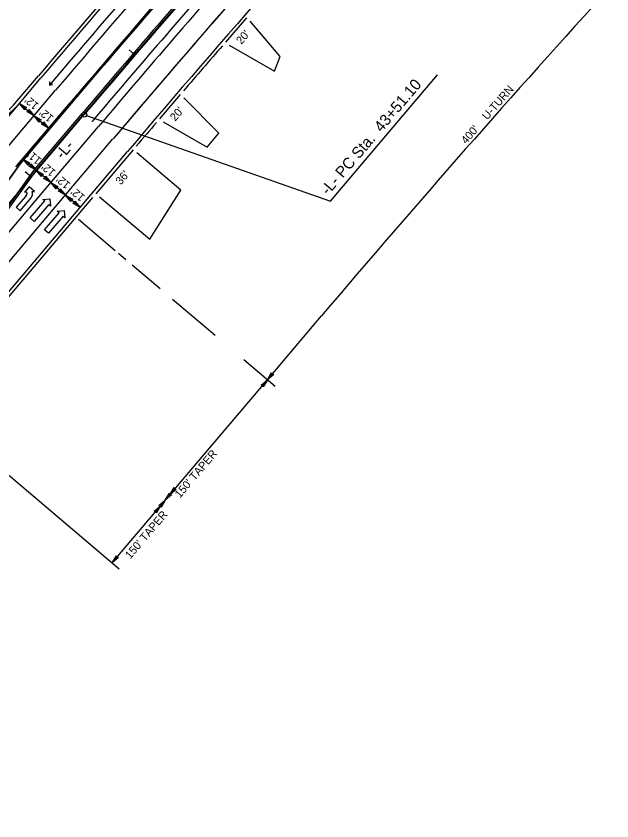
# Model space of a CAD drawing. Extents: x 1761082 to 1764358, y 421907 to 425434.
# Drawn here: x 1763418 to 1763790, y 424026 to 424529 of the extents above; entities that cross this region are included whole.
import ezdxf

# ---------------------------------------------------------------- set-up
doc = ezdxf.new("R2010")
doc.units = 0
for name, color, linetype in [('MARK HOOKS CENTER STRAIGHT LEFT TURN ARROW CELL', 7, 'Continuous'), ('MARK HOOKS STRAIGHT RIGHT TURN ARROW CELL', 7, 'Continuous'), ('MARK LEFT TURN ARROW CELL', 7, 'Continuous'), ('MARK ONLY WORD SYMBOL CELL', 7, 'Continuous'), ('MARK STRAIGHT RIGHT ARROW CELL', 7, 'Continuous'), ('MARK UTURN ARROW CELL', 7, 'Continuous'), ('Prop Conc Driveway', 7, 'Continuous'), ('Prop Mkg 3ft Min Skp 3ft Wide White', 7, 'Continuous'), ('Prop Mkg Skp Wht', 7, 'Continuous'), ('Prop Mkg Solid White Diagonals', 7, 'Continuous'), ('Prop Mkg Solid White Edge Line', 7, 'Continuous'), ('Prop Mkg Solid White Lane Line', 7, 'Continuous'), ('Prop Mkg Solid Yel Skip LT', 7, 'Continuous'), ('Prop Mkg Solid Yel Skip RT', 7, 'Continuous'), ('Prop Mkg Solid Yellow Diagonals', 7, 'Continuous'), ('Prop Mkg Solid Yellow Edge Line', 7, 'Continuous'), ('Prop Mkg Solid Yellow Lane Line', 7, 'Continuous'), ('Scratch_Level_0', 7, 'Continuous'), ('Scratch_Level_1', 7, 'Continuous')]:
    doc.layers.add(name, color=color, linetype=linetype)

msp = doc.modelspace()

# ---------------------------------------------------------------- linework, layer by layer
at = {"layer": 'MARK HOOKS CENTER STRAIGHT LEFT TURN ARROW CELL'}
for p, q in [((1763491.94, 424504.4), (1763488.15, 424507.65)), ((1763427.18, 424428.2), (1763423.37, 424431.43))]:
    msp.add_line(p, q, dxfattribs=at)
at = {"layer": 'MARK LEFT TURN ARROW CELL'}
for p, q in [((1763418.12, 424475.51), (1763431.6, 424491.43)), ((1763290.14, 424208.41), (1763465.55, 424415.48))]:
    msp.add_line(p, q, dxfattribs=at)
for centre, radius, start, end in [((1769289.17, 419529.14), 7676.94, 138.803366, 139.730103), ((1769289.17, 419529.14), 7601.94, 139.061862, 139.343024), ((1763381.5, 424506.54), 48, 261.3879, 319.7301), ((1769289.17, 419529.14), 7601.94, 139.538986, 139.684921)]:
    msp.add_arc(centre, radius, start, end, dxfattribs=at)
at = {"layer": 'MARK ONLY WORD SYMBOL CELL'}
for p, q in [((1763561.63, 424527.61), (1763548.5, 424512.52)), ((1763520.2, 424479.74), (1763507.2, 424464.55)), ((1763490.76, 424445.23), (1763467.49, 424417.76))]:
    msp.add_line(p, q, dxfattribs=at)
at = {"layer": 'MARK STRAIGHT RIGHT ARROW CELL'}
msp.add_line((1763060.78, 423995.7), (1763460.21, 424467.19), dxfattribs=at)
msp.add_arc((1769289.17, 419529.14), 7639.44, 137.617012, 139.730103, dxfattribs=at)
at = {"layer": 'MARK UTURN ARROW CELL'}
msp.add_lwpolyline([(1763461.63, 424466.69), (1763614.03, 424413.18), (1763680.83, 424492.03)], dxfattribs=at)
msp.add_circle((1763460.21, 424467.19), 1.5, dxfattribs=at)
at = {"layer": 'Prop Conc Driveway'}
for p, q in [((1763582.55, 424503.58), (1763563.89, 424525.64)), ((1763550.76, 424510.56), (1763579.06, 424494.39)), ((1763579.06, 424494.39), (1763582.55, 424503.58)), ((1763544.32, 424455.69), (1763522.48, 424477.79)), ((1763509.48, 424462.6), (1763537.04, 424446.86)), ((1763537.04, 424446.86), (1763544.32, 424455.69)), ((1763520.43, 424420.08), (1763493.05, 424443.29)), ((1763501.08, 424389.31), (1763520.43, 424420.08)), ((1763469.78, 424415.83), (1763501.08, 424389.31))]:
    msp.add_line(p, q, dxfattribs=at)
at = {"layer": 'Prop Mkg 3ft Min Skp 3ft Wide White'}
msp.add_line((1763060.78, 423995.7), (1763460.21, 424467.19), dxfattribs=at)
msp.add_arc((1769289.17, 419529.14), 7639.44, 137.617012, 139.730103, dxfattribs=at)
at = {"layer": 'Prop Mkg Skp Wht'}
for p, q in [((1763419.65, 424474.22), (1763433.13, 424490.13)), ((1763191.95, 424095.61), (1763487.3, 424444.24))]:
    msp.add_line(p, q, dxfattribs=at)
for centre, radius, start, end in [((1769289.17, 419529.14), 7603.94, 137.617012, 139.730103), ((1769289.17, 419529.14), 7674.94, 138.158837, 139.730103), ((1763381.5, 424506.54), 50, 261.3879, 319.7301)]:
    msp.add_arc(centre, radius, start, end, dxfattribs=at)
at = {"layer": 'Prop Mkg Solid White Diagonals'}
for p, q in [((1763452.01, 424474.14), (1763420.16, 424436.54)), ((1763429.37, 424433.1), (1763459.07, 424468.16)), ((1763420.16, 424436.54), (1763330.53, 424311.79)), ((1763335.43, 424303.26), (1763429.37, 424433.1))]:
    msp.add_line(p, q, dxfattribs=at)
for radius, start in [(7650.19, 137.617012), (7640.94, 138.645864)]:
    msp.add_arc((1769289.17, 419529.14), radius, start, 139.730103, dxfattribs=at)
at = {"layer": 'Prop Mkg Solid White Edge Line'}
msp.add_arc((1769289.17, 419529.14), 7615.94, 137.617012, 139.730103, dxfattribs=at)
at = {"layer": 'Prop Mkg Solid White Lane Line'}
for p, q in [((1763420.16, 424436.54), (1763452.01, 424474.14)), ((1763429.37, 424433.1), (1763459.07, 424468.16)), ((1763330.53, 424311.79), (1763420.16, 424436.54)), ((1763429.37, 424433.1), (1763335.43, 424303.26))]:
    msp.add_line(p, q, dxfattribs=at)
for radius in [7650.19, 7640.94]:
    msp.add_arc((1769289.17, 419529.14), radius, 138.645864, 139.730103, dxfattribs=at)
at = {"layer": 'Prop Mkg Solid Yel Skip RT'}
for p, q in [((1763419.65, 424474.22), (1763437.96, 424458.71)), ((1763457.62, 424409.21), (1763421.76, 424439.59)), ((1763479.44, 424382.18), (1763456.52, 424401.6)), ((1763486.21, 424376.45), (1763481.57, 424380.38)), ((1763507.52, 424358.39), (1763490.13, 424373.12)), ((1763542.04, 424329.15), (1763515.3, 424351.8)), ((1763574.58, 424301.58), (1763608.47, 424341.59)), ((1763579.49, 424297.42), (1763559.97, 424313.95)), ((1763477.62, 424187.13), (1763574.58, 424301.58)), ((1763482.07, 424183.36), (1763404.94, 424248.7))]:
    msp.add_line(p, q, dxfattribs=at)
msp.add_arc((1769289.17, 419529.14), 7445.13, 137.617012, 139.730103, dxfattribs=at)
at = {"layer": 'Prop Mkg Solid Yellow Diagonals'}
for p, q in [((1763425.88, 424422.16), (1763422.91, 424418.77)), ((1763429.19, 424419.26), (1763425.88, 424422.16)), ((1763422.91, 424418.77), (1763424.39, 424418.89)), ((1763427.71, 424419.14), (1763429.19, 424419.26)), ((1763423.64, 424416.24), (1763417.69, 424409.29)), ((1763420.19, 424407.14), (1763427.06, 424415.16)), ((1763426.4, 424402.63), (1763435.52, 424413.25)), ((1763434.39, 424414.23), (1763438.79, 424414.6)), ((1763435.52, 424413.25), (1763434.39, 424414.23)), ((1763438.79, 424414.6), (1763439.16, 424410.12)), ((1763417.69, 424409.29), (1763420.19, 424407.14)), ((1763438.03, 424411.1), (1763428.9, 424400.48)), ((1763439.16, 424410.12), (1763438.03, 424411.1)), ((1763443.31, 424406.85), (1763447.72, 424407.22)), ((1763447.72, 424407.22), (1763448.09, 424402.75)), ((1763428.9, 424400.48), (1763426.4, 424402.63)), ((1763435.33, 424395.25), (1763444.45, 424405.87)), ((1763446.95, 424403.72), (1763437.83, 424393.1)), ((1763444.45, 424405.87), (1763443.31, 424406.85)), ((1763448.09, 424402.75), (1763446.95, 424403.72)), ((1763437.83, 424393.1), (1763435.33, 424395.25))]:
    msp.add_line(p, q, dxfattribs=at)
for centre, radius, start, end in [((1763421.17, 424418.37), 3.27, 319.4106, 9.0688), ((1763422.61, 424417.92), 5.25, 328.0867, 13.3984)]:
    msp.add_arc(centre, radius, start, end, dxfattribs=at)
at = {"layer": 'Prop Mkg Solid Yellow Edge Line'}
for p, q in [((1763091.01, 424067.73), (1763442.28, 424482.38)), ((1763328.27, 424366.36), (1763419.65, 424474.22)), ((1763435.09, 424419.75), (1763468.99, 424459.75)), ((1763127.86, 424038.51), (1763478.14, 424452)), ((1763338.14, 424305.3), (1763435.09, 424419.75))]:
    msp.add_line(p, q, dxfattribs=at)
for radius, start in [(7662.94, 137.617012), (7627.94, 138.644778), (7615.94, 138.644778)]:
    msp.add_arc((1769289.17, 419529.14), radius, start, 139.730103, dxfattribs=at)
at = {"layer": 'Prop Mkg Solid Yellow Lane Line'}
for points in [[(1763422.97, 424470.25), (1763419.65, 424474.22), (1763424.15, 424471.6), (1763423.06, 424471.33)], [(1763425.48, 424470.43), (1763428.8, 424466.46), (1763424.3, 424469.09), (1763425.38, 424469.36)], [(1763432.13, 424462.5), (1763428.8, 424466.46), (1763433.3, 424463.84), (1763432.22, 424463.57)], [(1763434.63, 424462.68), (1763437.96, 424458.71), (1763433.46, 424461.33), (1763434.54, 424461.6)], [(1763425.09, 424435.62), (1763421.76, 424439.59), (1763426.26, 424436.96), (1763425.18, 424436.69)], [(1763426.83, 424436.45), (1763430.15, 424432.48), (1763425.65, 424435.1), (1763426.74, 424435.37)], [(1763433.48, 424428.51), (1763430.15, 424432.48), (1763434.66, 424429.85), (1763433.57, 424429.58)], [(1763435.98, 424428.69), (1763439.31, 424424.72), (1763434.81, 424427.35), (1763435.89, 424427.62)], [(1763442.64, 424420.75), (1763439.31, 424424.72), (1763443.81, 424422.1), (1763442.73, 424421.83)], [(1763445.14, 424420.93), (1763448.47, 424416.97), (1763443.96, 424419.59), (1763445.05, 424419.86)], [(1763451.79, 424413), (1763448.47, 424416.97), (1763452.97, 424414.34), (1763451.88, 424414.07)], [(1763454.3, 424413.18), (1763457.62, 424409.21), (1763453.12, 424411.83), (1763454.2, 424412.1)], [(1763570.61, 424298.26), (1763574.58, 424301.58), (1763571.95, 424297.08), (1763571.68, 424298.17)], [(1763578.55, 424304.91), (1763574.58, 424301.58), (1763577.2, 424306.09), (1763577.47, 424305)], [(1763517.66, 424233.04), (1763513.7, 424229.72), (1763516.32, 424234.22), (1763516.59, 424233.14)], [(1763506.83, 424222.98), (1763510.8, 424226.3), (1763508.18, 424221.8), (1763507.9, 424222.88)], [(1763514.77, 424229.63), (1763510.8, 424226.3), (1763513.42, 424230.8), (1763513.7, 424229.72)], [(1763503.94, 424219.56), (1763507.9, 424222.88), (1763505.28, 424218.38), (1763505.01, 424219.47)], [(1763481.59, 424190.46), (1763477.62, 424187.13), (1763480.24, 424191.63), (1763480.51, 424190.55)]]:
    msp.add_lwpolyline(points, close=True, dxfattribs=at)
at = {"layer": 'Scratch_Level_0'}
for p, q in [((1763417.55, 424434.61), (1763451.44, 424474.62)), ((1763430.15, 424432.48), (1763459.83, 424467.51)), ((1763430.15, 424432.48), (1763338.14, 424305.3))]:
    msp.add_line(p, q, dxfattribs=at)
for radius in [7650.94, 7639.94]:
    msp.add_arc((1769289.17, 419529.14), radius, 138.645864, 139.730103, dxfattribs=at)
at = {"layer": 'Scratch_Level_1'}
msp.add_lwpolyline([(1763438.47, 424485.61), (1763440.42, 424486.03), (1763439.11, 424486.37), (1763438.56, 424487.61)], close=True, dxfattribs=at)
msp.add_lwpolyline([(1763438.47, 424485.61), (1763440.42, 424486.03), (1763439.11, 424486.37), (1763438.56, 424487.61)], close=True, dxfattribs=at)
msp.add_lwpolyline([(1763438.47, 424485.61), (1763440.42, 424486.03), (1763439.11, 424486.37), (1763438.56, 424487.61)], close=True, dxfattribs=at)
for centre in [(1763438.47, 424485.61), (1763438.47, 424485.61), (1763438.47, 424485.61), (1763465.17, 424462.99), (1763465.17, 424462.99), (1763465.17, 424462.99)]:
    msp.add_circle(centre, 0.0417, dxfattribs=at)
for radius, start in [(7667.94, 138.0798), (7632.94, 138.727677)]:
    msp.add_arc((1769289.17, 419529.14), radius, start, 139.730103, dxfattribs=at)

# ---------------------------------------------------------------- texts
at = {"layer": 'MARK HOOKS STRAIGHT RIGHT TURN ARROW CELL'}
msp.add_text('-L-', height=7, rotation=49.7301, dxfattribs=at).set_placement((1763446.69, 424438.84))
at = {"layer": 'MARK UTURN ARROW CELL'}
msp.add_text('-L- PC Sta.  43+51.10', height=7, rotation=49.7301, dxfattribs=at).set_placement((1763612.59, 424416.46))
at = {"layer": 'Prop Mkg Solid Yel Skip LT'}
for s, rotation, p in [("20'", 49.0504, (1763558.31, 424510.68)), ('U-TURN', 48.8933, (1763711.95, 424463.5)), ("12'", 139.7301, (1763432.26, 424473.51)), ("20'", 49.5276, (1763517.03, 424462.78)), ("12'", 139.7301, (1763441.42, 424465.75)), ("400'", 48.8933, (1763698.8, 424448.43)), ("11'", 139.7301, (1763433.92, 424439.26)), ("12'", 139.7301, (1763442.77, 424431.77)), ("36'", 49.5276, (1763483, 424422.94)), ("12'", 139.7301, (1763451.93, 424424.01)), ("12'", 139.7301, (1763461.08, 424416.25)), ("150' TAPER", 49.7301, (1763519.97, 424227.31)), ("150' TAPER", 49.7301, (1763488.96, 424189.28))]:
    msp.add_text(s, height=5, rotation=rotation, dxfattribs=at).set_placement(p)

doc.saveas('drawing.dxf')
